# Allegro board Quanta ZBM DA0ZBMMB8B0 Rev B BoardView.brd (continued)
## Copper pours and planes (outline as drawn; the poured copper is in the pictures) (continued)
PPVAR_USB_C0_VIN_R on TOP (solid shape): 54.87,17.98 54.87,17.63 55.03,17.46 56.09,17.46 56.91,16.64 56.91,10 56.01,9.1 56.01,8.24 55.69,7.92 54.71,7.92 54.48,8.14 54.48,10.42 53.99,10.91 53.99,12.43 53.99,12.52 53.99,12.61 53.96,12.64 53.95,12.67 53.92,12.72 53.89,12.76 53.85,12.8 53.81,12.83 53.76,12.86 53.73,12.87 53.22,13.39 53.21,13.39 52.22,14.38 52.22,14.67 53.71,14.67 53.71,13.88 53.81,13.78 55.16,13.78 55.39,14 55.39,14.17 55.39,14.3 55.39,14.47 55.06,14.79 53.84,14.79 53.71,14.67 52.22,14.67 52.22,18.22 52.45,18.46 54.39,18.46
PPVAR_VBAT_U on BOTTOM (solid shape): 88.28,20.89 88.28,19.24 87.9,18.86 83.71,18.86 83.58,18.98 83.58,21.02 84.03,21.46 87.71,21.46
PPVAR_VCCIN on TOP (solid shape): outline of 1297 points within 125.46,52.11 161.05,69.2
PPVAR_VCCIN on BOTTOM (solid shape): outline of 3729 points within 124.8,57.21 161.01,74.77
PPVAR_VCCIN on IN2 (solid shape): outline of 141 points within 141.6,57.3 161.24,67.61
PPVAR_VCCIN on IN3 (solid shape): outline of 4236 points within 124.73,49.94 161.09,74.75
PPVAR_VCCIN on IN4 (solid shape): 161.11,64.01 161.11,56.72 160.67,56.28 147.62,56.28 140.92,62.99 140.92,64.32 141.15,64.55 143.96,64.55 144.84,63.67 144.84,61.48 145.3,61.02 146.39,59.62 148.09,59.08 148.14,59.08 148.97,59.19 149.73,59.53 149.75,59.54 150.24,59.54 151.6,60.9 151.6,64.14 152.42,64.96 160.16,64.96
PPVAR_VCCIN on IN5 (solid shape): 160.99,64.33 160.99,63.28 160.97,63.26 160.97,56.58 160.67,56.28 146.89,56.28 140.82,62.35 140.87,62.44 140.89,62.55 140.81,62.76 140.61,62.87 140.57,62.88 140.57,63.97 141.15,64.55 143.96,64.55 144.84,63.67 144.84,61.48 145.3,61.02 146.38,59.63 148.06,59.08 148.18,59.08 148.99,59.2 149.73,59.53 149.75,59.54 150.24,59.54 151.6,60.9 151.6,64.14 152.42,64.96 160.36,64.96
PPVAR_VCCIN_AUX on TOP (solid shape): outline of 781 points within 67.95,54.02 101.27,80.18
PPVAR_VCCIN_AUX on BOTTOM (solid shape): outline of 3105 points within 89.12,62.56 123.31,81.6
PPVAR_VCCIN_AUX on IN3 (solid shape): outline of 6007 points within 88.09,64.05 119.16,82.44
PPVAR_VCCIN_AUX on IN4 (solid shape): outline of 642 points within 73.51,61.09 100.28,79.65
PPVAR_VNNEXT on TOP (solid shape): 71.02,34.08 71.02,31.79 70.92,31.68 70.32,31.68 70.23,31.78 64.53,31.78 64.37,31.93 64.37,34.01 64.63,34.27 70.83,34.27
PPVAR_VNNEXT on IN2 (solid shape): outline of 1881 points within 74.43,56.49 110.58,70.29
PPVAR_VNNEXT on IN3 (solid shape): outline of 1256 points within 69.8,31.27 78.81,58.81
RSPK_N on TOP (solid shape): 29.87,26.42 29.87,24.79 29.78,24.7 28.85,24.7 28.77,24.78 28.77,26.56 28.95,26.73 29.56,26.73
RSPK_N on TOP (solid shape): 29.97,16.91 29.97,15.53 29.78,15.34 29.76,15.34 28.95,15.34 28.85,15.44 28.85,17.07 28.98,17.21 29.68,17.21
RSPK_N on BOTTOM (solid shape): 29.85,26.45 29.85,24.33 28.97,23.45 28.97,21.84 28.86,21.73 28.27,21.73 28.18,21.82 28.18,24.24 28.81,24.87 28.81,26.54 28.95,26.69 29.61,26.69
RSPK_P on TOP (solid shape): 28.51,26.48 28.51,24.82 28.4,24.7 27.69,24.7 27.69,24.71 27.59,24.71 27.48,24.82 27.48,26.52 27.69,26.73 28.26,26.73
RSPK_P on TOP (solid shape): 25.71,20.68 25.71,19.7 25.12,19.1 24.32,19.1 24.23,19.19 24.23,19.49 24.27,19.59 24.29,19.69 24.27,19.79 24.23,19.88 24.23,20.15 24.55,20.48 24.55,20.51 24.92,20.87 25.51,20.87
RSPK_P on BOTTOM (solid shape): 28.55,26.54 28.55,24.98 27.72,24.14 27.72,21.87 27.61,21.76 27,21.76 26.93,21.83 26.93,24.87 27.3,25.23 27.41,25.35 27.41,25.96 27.51,26.05 27.51,26.59 27.59,26.68 28.42,26.68
RSPK_R_N on TOP (solid shape): 29.79,14.95 29.79,14.16 29.16,13.53 27.91,13.53 27.51,13.93 26.43,13.93 26.43,14.24 27.91,14.24 28.67,14.99 29.75,14.99
RSPK_R_P on TOP (solid shape): 25.32,18.59 25.32,18.59 25.47,18.43 25.47,17.13 25.19,16.84 25.19,16.43 25.18,16.43 25.18,15.5 25.12,15.44 24.88,15.44 24.88,16.7 24.54,17.03 24.54,17.48 24.23,17.8 24.23,18.69 24.32,18.78 25.13,18.78
USB_C0_CC1 on BOTTOM (solid shape): 34.11,68.79 34.72,68.79 34.79,68.72 34.79,68.71 34.92,68.57 35.1,68.51 35.17,68.48 35.2,68.41 35.2,68.2 35.2,68.2 35.2,68.06 35.14,68 34.04,68 33.81,68.24 32.33,68.24 32.32,68.24 32.18,68.24 32.07,68.35 32.07,68.74 32.24,68.91 33.99,68.91
USB_C0_CC1_C on TOP (solid shape): 37.34,68.79 37.99,68.79 38.05,68.73 38.05,68.63 38,68.59 37.34,68.59 37.34,68.58 37.24,68.49 37.23,68.48 37.16,68.41 37.16,68.1 37.03,67.97 36.59,67.97 36.49,68.07 36.49,68.35 36.93,68.79 37.34,68.79
USB_C0_CC1_C on BOTTOM (solid shape): 37.09,68.64 37.09,68.07 37,67.98 35.5,67.98 35.45,68.03 35.45,68.51 35.74,68.8 36.93,68.8
USB_C0_CC2 on BOTTOM (solid shape): 33.9,67.82 35.07,67.82 35.2,67.69 35.2,67.31 35.07,67.18 32.39,67.18 32.25,67.31 32.25,67.89 32.35,67.98 33.74,67.98
USB_C0_CC2_C on TOP (solid shape): 38.1,68.25 38.1,67.68 37.58,67.15 36.66,67.15 36.58,67.23 36.58,67.55 36.71,67.69 37.11,67.69 37.34,67.91 37.34,68.39 37.97,68.39
USB_C0_CC2_C on BOTTOM (solid shape): 37.09,67.6 37.09,67.12 36.88,66.91 35.84,66.91 35.45,67.31 35.45,67.61 35.52,67.68 37.01,67.68
USB_C0_VX1 on TOP (solid shape): 55.27,20.12 57.89,20.12 58.77,19.24 58.84,19.24 58.91,19.17 59.52,19.17 59.52,19 59.49,18.97 58.91,18.97 58.91,18.96 58.23,18.96 58.22,18.99 58.06,19.21 57.81,19.29 57.55,19.21 57.4,18.99 57.38,18.95 56.42,18.95 56.05,18.59 52.22,18.59 51.98,18.35 51.96,18.35 51.96,14.29 51.83,14.16 49.17,14.16 49.04,14.29 49.04,18.73 48.53,19.24 48.53,21.4 48.72,21.59 53.8,21.59
USB_C0_VX2 on TOP (solid shape): 59.38,26.83 59.38,25.35 58.91,24.88 48.76,24.88 48.41,25.23 48.41,27.39 48.69,27.67 58.54,27.67
N17740383 on TOP (solid shape): 178,55.15 178,54.96 177.97,54.92 177.27,54.92 177.13,55.07 177.13,55.14 176.87,55.4 175.48,55.4 175.35,55.53 175.35,56.29 175.45,56.39 176.76,56.39
N17740385 on TOP (solid shape): 174.97,56.31 174.97,54.54 174.84,54.41 174.67,54.41 174.66,54.42 174.07,54.42 173.95,54.54 173.95,56.31 174.08,56.44 174.84,56.44
N17742434 on TOP (solid shape): 168.88,73.66 168.88,72.58 169.57,71.89 178.96,71.89 179.12,71.73 179.12,66.12 178.81,65.81 173.57,65.81 172.54,64.78 172.54,60.82 171.94,60.22 167.86,60.22 167.48,60.61 167.48,73.62 167.78,73.93 168.61,73.93
N17743042 on TOP (solid shape): 158.13,82.14 158.13,80.31 158.1,80.29 157.88,79.95 158.1,79.6 158.13,79.59 158.13,78.29 158.51,77.91 159.4,77.91 159.53,77.79 159.53,77.28 159.38,77.14 154.75,77.14 154.35,77.54 154.35,79.42 154.49,79.56 154.49,82.98 154.58,83.07 157.2,83.07
N17745848 on TOP (solid shape): 54.74,50.72 54.76,50.73 59.84,50.73 60.02,50.55 60.02,44.77 59.42,44.16 51.42,44.16 49.59,46 49.59,47.52 48.99,48.12 46.94,48.12 45.02,50.03 45.02,50.91 45.1,50.99 54.47,50.99
N17746077 on TOP (solid shape): 53.49,57.22 53.49,57.21 53.61,57.08 53.61,56.2 54.5,55.31 54.5,54.54 54.37,54.42 53.49,54.42 52.54,55.36 52.54,55.9 52.7,56.2 52.54,56.49 52.13,56.9 52.13,57.13 52.16,57.21 52.16,57.29 52.06,57.54 51.81,57.64 51.73,57.64 51.65,57.61 51.57,57.69 51.57,57.79 51.65,57.87 52.83,57.87
N17746099 on TOP (solid shape): 53.66,61.85 53.99,61.85 54.1,61.74 54.1,61.14 53.92,60.96 52.99,60.96 52.84,60.82 52.84,60.81 52.77,60.69 52.75,60.56 52.77,60.43 52.84,60.32 52.84,59.36 52.76,59.27 52.4,59.27 52.4,59.27 51.63,59.27 51.54,59.37 51.54,59.54 51.4,59.68 51.27,59.68 51.21,59.74 51.21,60.51 51.22,60.52 51.22,61.62 51.46,61.86 53.66,61.86
N17746814 on TOP (solid shape): 187.08,44.05 187.08,43.91 187.08,43.89 187.04,43.8 187.02,43.7 187.04,43.6 187.08,43.5 187.08,43.31 187.04,43.21 187.02,43.11 187.04,43.01 187.08,42.91 187.08,42.72 187.04,42.62 187.02,42.52 187.04,42.41 187.08,42.32 187.08,42.08 187.04,41.98 187.02,41.88 187.03,41.79 187.06,41.71 187.08,41.68 186.98,41.58 186.46,41.58 186.17,41.87 186.17,42.05 185.6,42.62 185.6,43.44 185.64,43.53 185.74,43.54 185.82,43.51 185.9,43.5 186.15,43.6 186.25,43.86 186.23,43.97 186.18,44.08 186.15,44.11 186.29,44.25 186.89,44.25
N17746864 on TOP (solid shape): 185.09,35.5 185.09,35.46 185.09,35.39 185.12,35.32 185.13,35.31 185.13,35.21 185.38,34.95 185.38,34.7 185.39,34.69 185.39,34.4 185.22,34.22 184.97,34.22 184.49,34.7 184.49,35.46 184.58,35.55 184.94,35.55 184.98,35.59 185,35.59
N17747083 on TOP (solid shape): 61.61,35.75 61.61,35.72 61.91,35.35 62.34,35.56 62.35,35.59 63.01,35.59 63.16,35.44 63.16,34.65 63.16,34.43 63.47,34.12 63.47,31.92 63.42,31.87 61.01,31.87 60.85,32.03 60.85,34.04 60.41,34.48 60.41,35.71 60.54,35.84 61.52,35.84
N17747309 on TOP (solid shape): 65.65,38.67 65.65,34.66 65.48,34.48 63.53,34.48 63.32,34.7 63.32,37.36 63.06,37.62 61.88,37.62 61.79,37.52 61.72,37.47 61.66,37.4 61.37,37.11 60.54,37.11 60.41,37.24 60.41,37.85 61.58,39.02 65.31,39.02
N17749264 on TOP (solid shape): 38.45,36.56 38.45,35.1 38.93,34.61 38.93,33.87 39.24,33.57 39.24,33.36 39.21,33.33 38.38,33.33 38.06,33.65 38.06,34.38 37.11,35.33 37.11,36.62 37.24,36.75 38.26,36.75
N17749266 on TOP (solid shape): 38,38.09 38,37.24 37.9,37.15 37.23,37.15 36.72,36.64 35.96,36.64 35.71,36.89 35.71,38.03 35.96,38.29 37.8,38.29
N17749576 on TOP (solid shape): 71.32,27.51 71.32,26.28 72.02,25.58 73.14,25.58 73.14,25.28 72.23,25.28 72.23,25.27 71.7,25.27 71.66,25.28 71.63,25.28 71.37,25.18 71.27,24.93 71.27,24.89 71.28,24.85 71.27,24.85 71.27,24.7 71.11,24.54 69.47,24.54 67.93,26.08 67.93,27.48 68.08,27.63 71.2,27.63
N17750770 on TOP (solid shape): 37.89,46.69 37.89,46.62 37.88,46.61 37.82,46.51 37.81,46.39 37.81,46.33 37.82,46.17 37.89,46.03 37.89,45.75 37.87,45.72 37.87,45.69 37.87,45.49 37.87,45.46 37.89,45.43 37.89,45.3 37.87,45.27 37.87,45.24 37.87,45.04 37.87,45.01 37.89,44.98 37.89,44.6 37.87,44.52 37.86,44.46 37.87,44.4 37.89,44.33 37.89,43.28 38.38,42.78 38.45,42.78 38.54,42.69 38.54,42.43 38.49,42.38 37.45,42.38 37.16,42.67 37.16,45.25 36.54,45.87 36.54,47.02 36.67,47.14 37.43,47.14
N17754636 on TOP (solid shape): 83.83,56.87 84.17,56.87 84.18,56.86 85.12,56.86 85.36,56.62 85.36,55.64 85.07,55.36 82.92,55.36 82.65,55.63 82.65,57.11 82.77,57.24 83.47,57.24
N18159921 on TOP (solid shape): 38.1,69.14 38.1,69.04 38.04,68.99 36.84,68.99 36.09,68.24 36.09,67.86 36.02,67.79 35.42,67.79 35.36,67.85 35.36,68.27 36.11,69.03 36.24,69.03 36.4,69.18 38.06,69.18
N19267926 on TOP (solid shape): 52.43,13.18 52.43,12.44 52.34,12.35 50.95,12.35 50.92,12.39 50.92,12.83 51.34,13.25 52.36,13.25
N19268068 on TOP (solid shape): 55.26,14.41 55.26,14.06 55.11,13.9 53.87,13.9 53.84,13.93 53.84,14.61 53.9,14.67 55.01,14.67
N19268072 on TOP (solid shape): 59.47,30.34 59.47,29.55 59.43,29.51 58.22,29.51 58.08,29.64 58.08,30.37 58.2,30.48 59.33,30.48
N19268120 on TOP (solid shape): 48.41,14.79 48.72,14.79 48.83,14.69 48.83,14 48.76,13.94 47.23,13.94 47.01,14.16 47.01,14.67 47.14,14.79 48.41,14.79
N19268132 on TOP (solid shape): 58.85,24.47 58.85,23.17 58.65,22.97 58.26,22.97 57.79,23.44 57.79,24.37 57.95,24.52 58.8,24.52
N19268231 on TOP (solid shape): 61.13,22.69 61.13,21.94 61.16,21.92 61.16,21.91 61.17,21.79 61.23,21.68 61.23,21.45 61.19,21.36 61.18,21.27 61.19,21.19 61.22,21.12 61.24,21.08 61.13,20.98 60.94,20.98 60.87,21.05 60.88,21.08 60.9,21.15 60.9,21.22 60.82,21.46 60.61,21.59 60.57,21.6 60.57,22.7 60.66,22.79 61.03,22.79

Small or netless copper shapes (teardrops, artwork), in the pictures only: 16 on TOP, 2 on BOTTOM, 2 on IN1, 54 on IN2, 13 on IN3

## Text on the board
Ref Des/Silkscreen Bottom: DA0ZBMMB8B0 REV:B | Please do not print out the lines with 0.39mils/0.01mm in width
User.Comments: 198.2 | 16x30 | 16x35 | 30x32 | 89.4 | 0.05 | 3 | ` | n | 1
Ref Des/Silkscreen Top: MODEL:ZBM | DA0ZBMMB8B0 | REV:B | Please do not print out the lines with 0.39mils/0.01mm in width
User.26: AGND_HP | GND
User.36: 0.05 | 3 | ` | n | 1
User.45: FIGURE | TYPE | Circle | Oblong | SIZE | 8.0 | 10.0 | 14.0 | 18.0 | 32.0 | 35.0 | 40.0 | 118.0 | 244.0 | 51.0 | 157.0 | 38.0x20.0 | 43.0x20.0 | 47.0x20.0 | 59.0x20.0 | 59.0x24.0 | 87.0x28.0 | 102.0x28.0 | 130.0x118.0 | DRILL CHART: TOP to BOTTOM | ALL UNITS ARE IN MILS | PLATED | NON-PLATED | ROTATION | - | 90.000 | 0.000 | QTY | 1302 | 2233 | 563 | 12 | 9 | 2 | 4 | 10 | 1 | 4143 | 7 | 26 | TOTAL HOLES:
